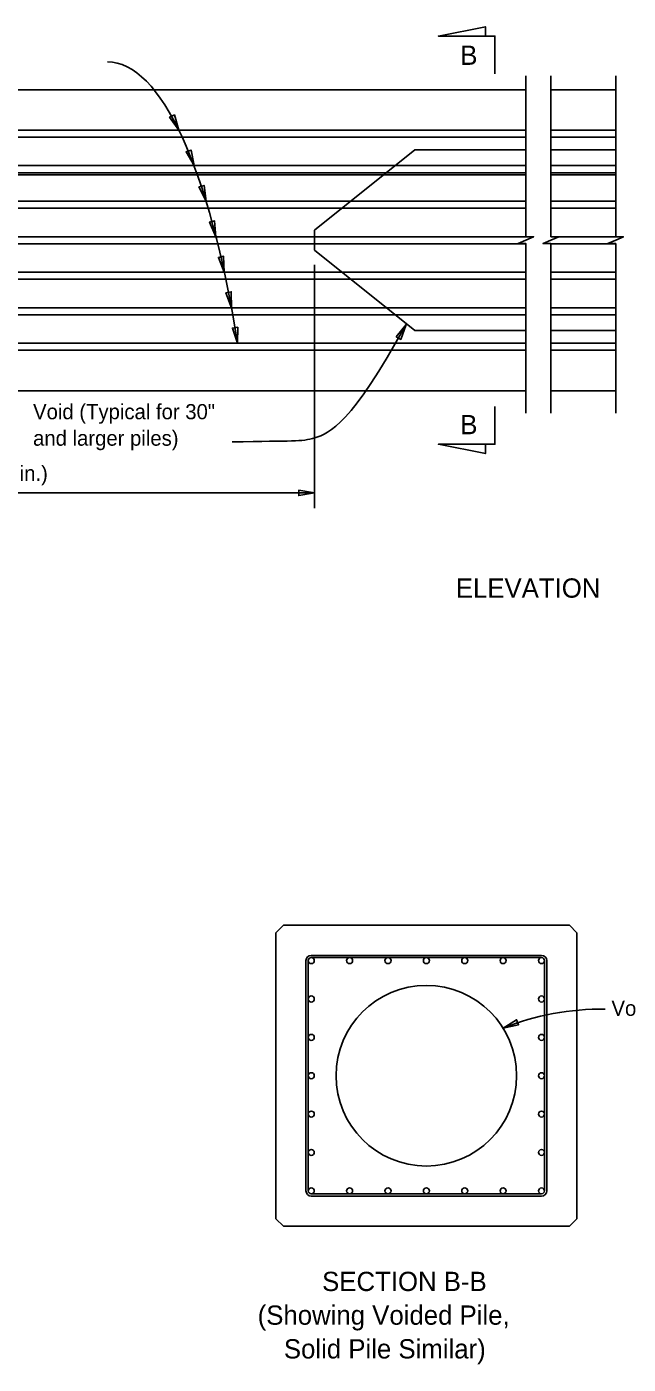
# Model space of a CAD drawing. Extents: x 0 to 36.1, y -3.7 to 15.
# Drawn here: x 6.87 to 10.86, y 3.9 to 12.79 of the extents above; entities that cross this region are included whole.
import ezdxf

# ---------------------------------------------------------------- set-up
doc = ezdxf.new("R2010")
doc.units = 0
for name, color, linetype in [('AdhocPoint_dp', 7, 'Continuous'), ('Leader', 7, 'Continuous'), ('Miscellaneous', 7, 'Continuous'), ('PileConc', 7, 'Continuous'), ('PileConc_h', 7, 'Continuous'), ('PlotBorder_dp', 7, 'Continuous'), ('PrestressSteel', 7, 'Continuous'), ('Symbols', 7, 'Continuous')]:
    doc.layers.add(name, color=color, linetype=linetype)

msp = doc.modelspace()

# ---------------------------------------------------------------- linework, layer by layer
at = {"layer": 'Leader'}
msp.add_arc((10.6849, 4.5123), 1.7476, 89.13531, 111.92522, dxfattribs=at)
msp.add_ellipse((7.3706, 8.4669), major_axis=(-0.0321, -4.0884), ratio=0.256409, start_param=2.146255, end_param=3.141593, dxfattribs=at)
at = {"layer": 'Miscellaneous'}
for p, q in [((10.1834, 11.8176), (5.5842, 11.8176)), ((10.1834, 11.8026), (5.5842, 11.8026)), ((10.35, 11.8176), (10.7805, 11.8176)), ((10.35, 11.8026), (10.7805, 11.8026))]:
    msp.add_line(p, q, dxfattribs=at)
at = {"layer": 'PileConc'}
for p, q in [((0.841, 12.3693), (10.1834, 12.3693)), ((10.7805, 12.3693), (10.35, 12.3693)), ((0.841, 10.3693), (10.1834, 10.3693)), ((10.7805, 10.3693), (10.35, 10.3693)), ((8.5725, 6.8172), (8.5225, 6.7672)), ((8.5225, 6.7672), (8.5225, 4.8672)), ((8.5725, 6.8172), (10.4725, 6.8172)), ((10.4725, 6.8172), (10.5225, 6.7672)), ((10.5225, 6.7672), (10.5225, 4.8672)), ((8.5225, 4.8672), (8.5725, 4.8172)), ((8.5725, 4.8172), (10.4725, 4.8172)), ((10.4725, 4.8172), (10.5225, 4.8672))]:
    msp.add_line(p, q, dxfattribs=at)
msp.add_circle((9.5224, 5.8172), 0.6, dxfattribs=at)
at = {"layer": 'PileConc_h'}
for p, q in [((9.4452, 11.9693), (8.7785, 11.4359)), ((9.4452, 11.9693), (10.1834, 11.9693)), ((10.7805, 11.9693), (10.35, 11.9693)), ((8.7785, 11.3026), (8.7785, 11.4359)), ((9.4452, 10.7693), (8.7785, 11.3026)), ((9.4452, 10.7693), (10.1834, 10.7693)), ((10.7805, 10.7693), (10.35, 10.7693))]:
    msp.add_line(p, q, dxfattribs=at)
at = {"layer": 'PlotBorder_dp'}
for p, q in [((8.7785, 11.2066), (8.7785, 9.5876)), ((4.7785, 9.6904), (8.7785, 9.6904))]:
    msp.add_line(p, q, dxfattribs=at)
for points in [[(10.1834, 10.2207), (10.1834, 11.3468), (10.1317, 11.3468), (10.1834, 11.3693), (10.235, 11.3918), (10.1834, 11.3918), (10.1834, 12.4621)], [(10.35, 10.2207), (10.35, 11.3468), (10.2983, 11.3468), (10.35, 11.3693), (10.4016, 11.3918), (10.35, 11.3918), (10.35, 12.4621)], [(10.7805, 10.2207), (10.7805, 11.3468), (10.7289, 11.3468), (10.7805, 11.3693), (10.8322, 11.3918), (10.7805, 11.3918), (10.7805, 12.4621)]]:
    msp.add_lwpolyline(points, dxfattribs=at)
for points in [[(7.8779, 12.1005), (7.8479, 12.2017), (7.8162, 12.1862)], [(7.9787, 11.8645), (7.9586, 11.9682), (7.9256, 11.9558)], [(8.0585, 11.6286), (8.045, 11.7333), (8.0112, 11.723)], [(8.1244, 11.3927), (8.1157, 11.4979), (8.0815, 11.4892)], [(8.1799, 11.1568), (8.1751, 11.2623), (8.1406, 11.2548)], [(8.2272, 10.9208), (8.2256, 11.0264), (8.1909, 11.02)], [(8.2676, 10.685), (8.2687, 10.7906), (8.2339, 10.7851)], [(8.7785, 9.6904), (8.6744, 9.6728), (8.6744, 9.7081)], [(10.0323, 6.1335), (10.1355, 6.156), (10.1223, 6.1888)]]:
    msp.add_lwpolyline(points, close=True, dxfattribs=at)
msp.add_open_spline([(8.2331, 10.0289), (8.6457, 10.038), (8.7281, 10.0179), (9.0272, 10.1508), (9.3872, 10.8099)], degree=3, dxfattribs=at)
at = {"layer": 'PrestressSteel'}
for p, q in [((10.1834, 12.1005), (0.7785, 12.1005)), ((10.35, 12.1005), (10.7805, 12.1005)), ((10.1834, 12.0536), (5.1518, 12.0536)), ((10.35, 12.0536), (10.7805, 12.0536)), ((10.1834, 11.8645), (5.1137, 11.8645)), ((10.35, 11.8645), (10.7805, 11.8645)), ((10.1834, 11.8176), (5.1187, 11.8176)), ((10.35, 11.8176), (10.7805, 11.8176)), ((10.1834, 11.5817), (5.3401, 11.5817)), ((10.1834, 11.6286), (5.3518, 11.6286)), ((10.35, 11.6286), (10.7805, 11.6286)), ((10.35, 11.5817), (10.7805, 11.5817)), ((10.1834, 11.3927), (5.216, 11.3927)), ((10.35, 11.3927), (10.7805, 11.3927)), ((10.1834, 11.3458), (5.2267, 11.3458)), ((10.35, 11.3458), (10.7805, 11.3458)), ((10.1834, 11.1568), (5.1137, 11.1568)), ((10.1834, 11.1099), (5.1137, 11.1099)), ((10.35, 11.1568), (10.7805, 11.1568)), ((10.35, 11.1099), (10.7805, 11.1099)), ((10.1834, 10.9208), (5.1137, 10.9208)), ((10.1834, 10.8739), (5.1137, 10.8739)), ((10.35, 10.9208), (10.7805, 10.9208)), ((10.35, 10.8739), (10.7805, 10.8739)), ((10.1834, 10.685), (5.1125, 10.685)), ((10.35, 10.685), (10.7805, 10.685)), ((10.1834, 10.6381), (0.7785, 10.6381)), ((10.35, 10.6381), (10.7805, 10.6381)), ((8.7225, 6.5822), (8.7225, 5.0523)), ((8.7375, 6.5822), (8.7375, 5.0523)), ((8.7575, 6.6172), (10.2875, 6.6172)), ((8.7575, 6.6022), (10.2875, 6.6022)), ((10.3074, 6.5822), (10.3074, 5.0523)), ((10.3225, 6.5822), (10.3225, 5.0523)), ((8.7575, 5.0323), (10.2875, 5.0323)), ((8.7575, 5.0172), (10.2875, 5.0172))]:
    msp.add_line(p, q, dxfattribs=at)
for centre in [(8.7575, 6.5822), (9.0125, 6.5822), (9.2675, 6.5822), (9.5224, 6.5822), (9.7774, 6.5822), (10.0324, 6.5822), (10.2874, 6.5822), (8.7575, 6.3272), (10.2874, 6.3272), (8.7575, 6.0722), (10.2874, 6.0722), (8.7575, 5.8172), (10.2874, 5.8172), (8.7575, 5.5623), (10.2874, 5.5623), (8.7575, 5.3073), (10.2874, 5.3073), (8.7575, 5.0523), (9.0125, 5.0523), (9.2675, 5.0523), (9.5224, 5.0523), (9.7774, 5.0523), (10.0324, 5.0523), (10.2874, 5.0523)]:
    msp.add_circle(centre, 0.02, dxfattribs=at)
for centre, start, end in [((8.7575, 6.5822), 90, 180), ((10.2874, 6.5822), 0, 90), ((8.7575, 5.0523), 180, 270), ((10.2874, 5.0523), 270, 0)]:
    msp.add_arc(centre, 0.035, start, end, dxfattribs=at)
at = {"layer": 'Symbols'}
for points in [[(9.9774, 12.475), (9.9774, 12.725), (9.6024, 12.725), (9.9149, 12.7875), (9.9149, 12.725), (9.9774, 12.725)], [(9.3218, 10.727), (9.3872, 10.8099), (9.3527, 10.7101)], [(9.9774, 10.2635), (9.9774, 10.0135), (9.6024, 10.0135), (9.9149, 9.951), (9.9149, 10.0135), (9.9774, 10.0135)]]:
    msp.add_lwpolyline(points, close=True, dxfattribs=at)

# ---------------------------------------------------------------- texts
at = {"layer": 'AdhocPoint_dp'}
for s, height, p in [('B', 0.128, (9.7478, 12.5343)), ('B', 0.128, (9.7478, 10.0799)), ('2D (Min.)', 0.1008, (6.4531, 9.7702)), ('ELEVATION', 0.128, (9.7181, 8.994)), ('SECTION B-B', 0.128, (8.8297, 4.3867)), ('(Showing Voided Pile,', 0.128, (8.4014, 4.1627)), ('Solid Pile Similar)', 0.128, (8.5757, 3.9387))]:
    msp.add_text(s, height=height, dxfattribs=at).set_placement(p)
at = {"layer": 'PlotBorder_dp'}
for s, p in [('Void (Typical for 30" ', (6.9092, 10.1795)), ('and larger piles)', (6.9092, 10.0035)), ('Void', (10.7523, 6.2153))]:
    msp.add_text(s, height=0.1008, dxfattribs=at).set_placement(p)

doc.saveas('drawing.dxf')
